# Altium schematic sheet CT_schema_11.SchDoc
size 386 x 278 mm
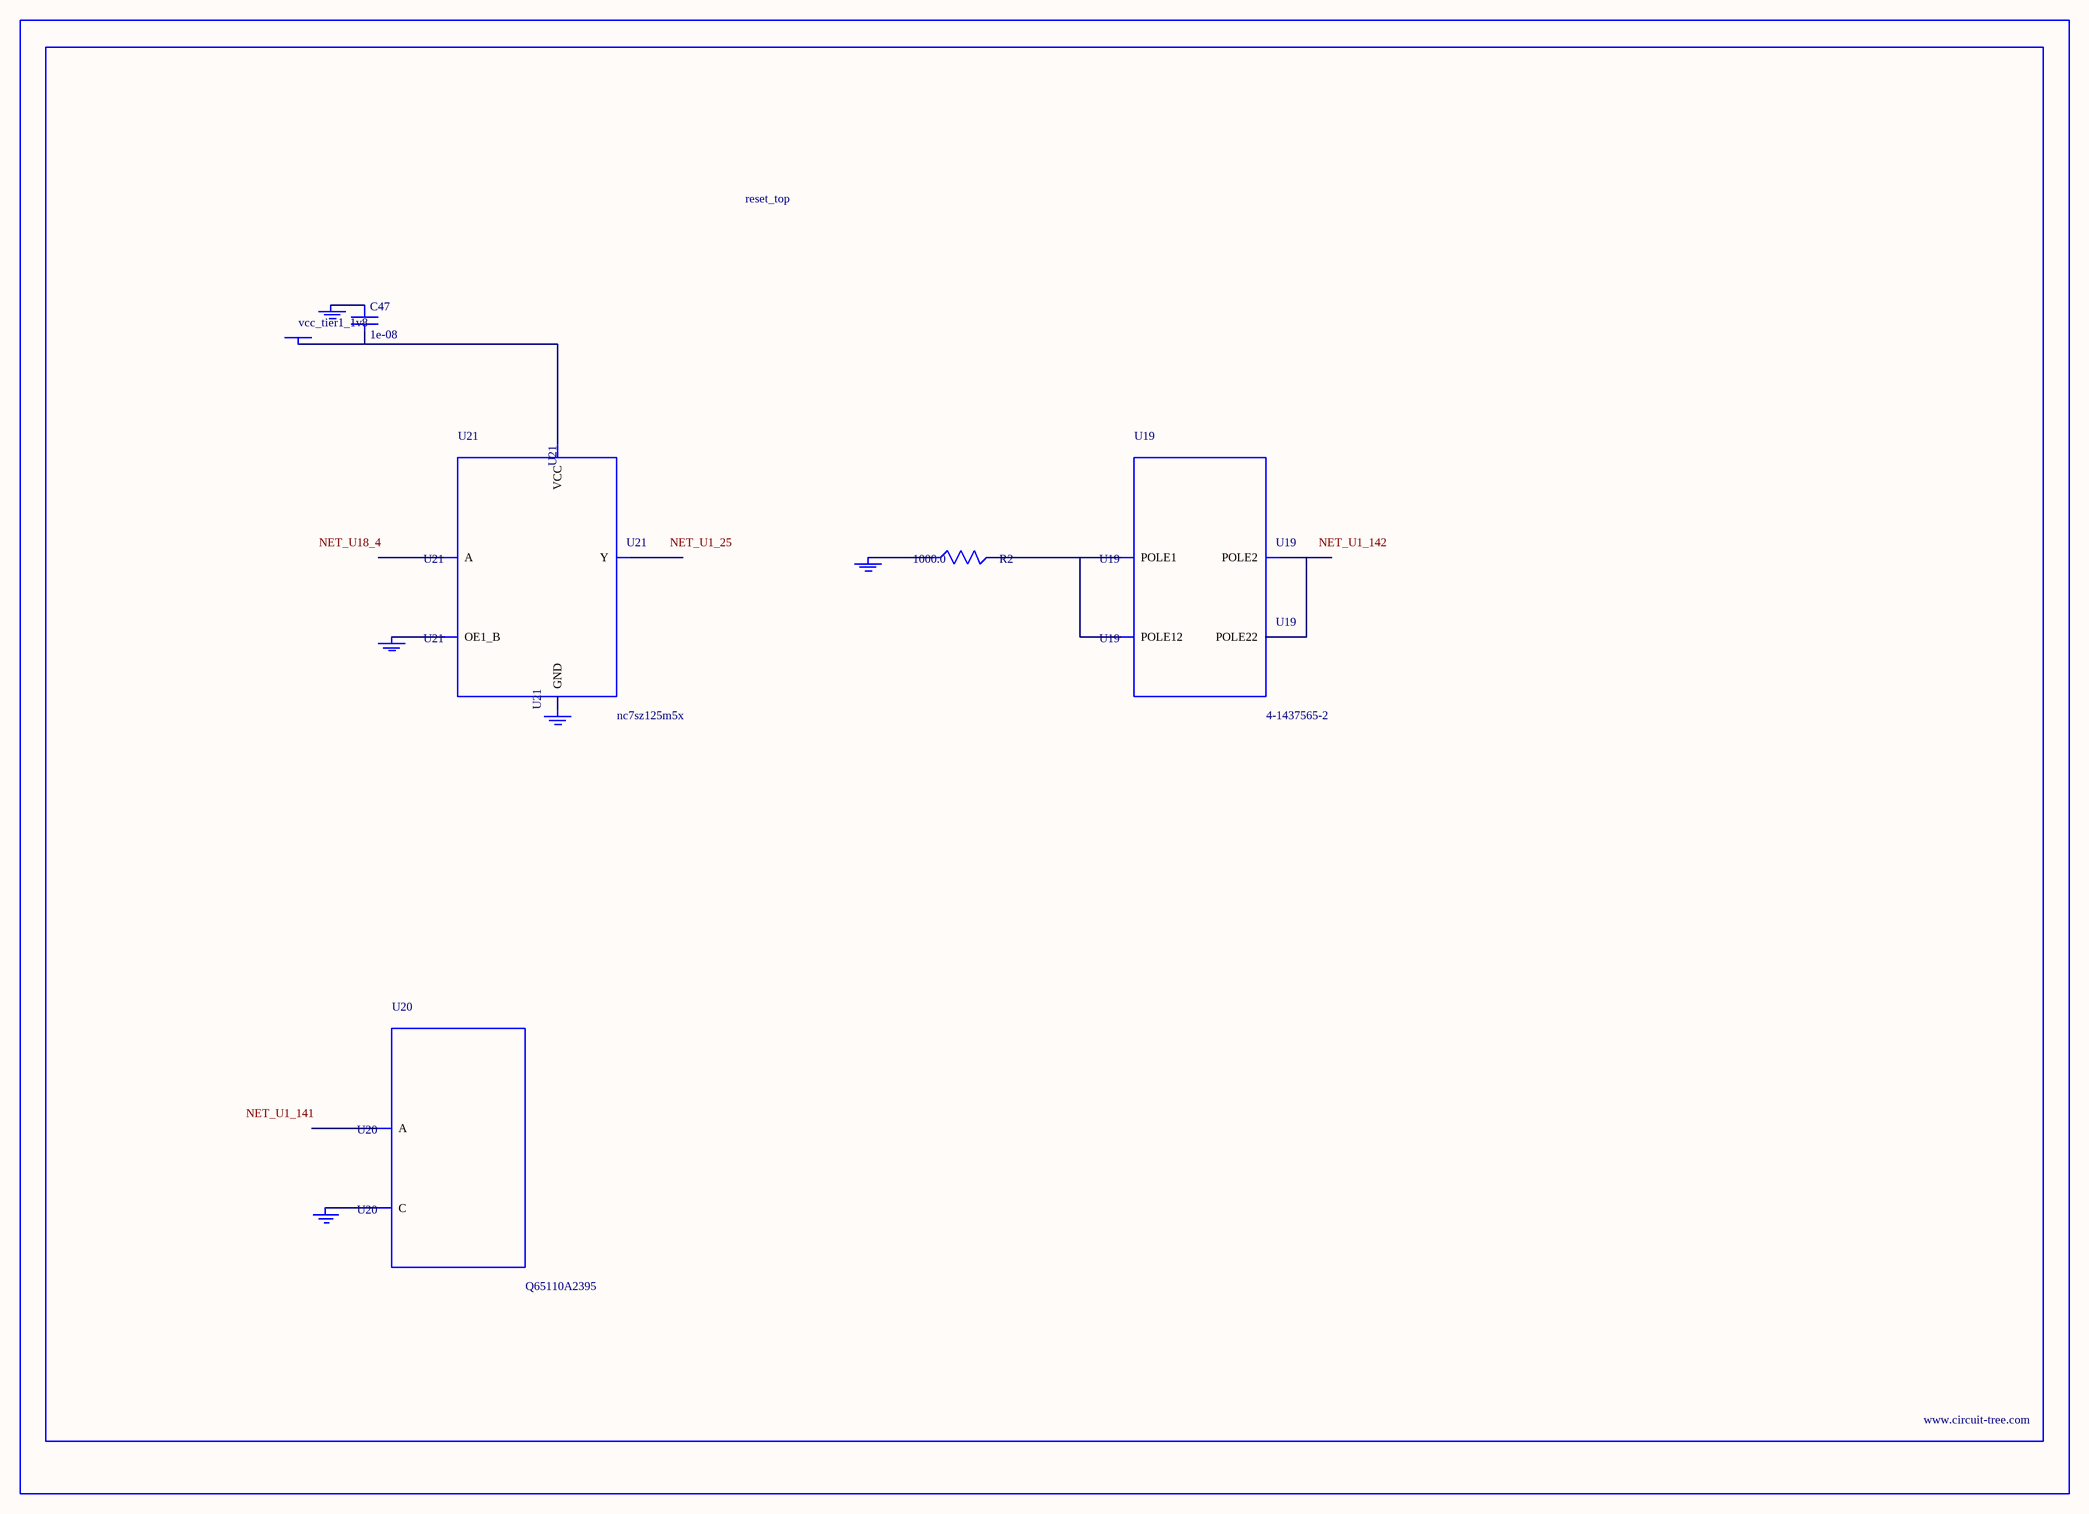
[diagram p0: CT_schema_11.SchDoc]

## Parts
BORDER10  (no value)
C47  1e-08  [C0402]
GND_INSTANCE_10_0  (no value)
GND_INSTANCE_10_1  (no value)
GND_INSTANCE_10_2  (no value)
GND_INSTANCE_10_3  (no value)
GND_INSTANCE_10_4  (no value)
POWER_INSTANCE_10_0  vcc_tier1_1v8
R2  1000.0  [R0603]
U19  4-1437565-2  [SW_4-1437565-2]
U20  Q65110A2395  [LGM67K-G1J2-24-Z]
U21  nc7sz125m5x  [NC7SZ125M5X]

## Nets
NetC47_1: C47.1 GND_INSTANCE_10_2.0(GND)
NetC47_2: C47.2 POWER_INSTANCE_10_0.0(PWR) U21.5(VCC)
NetGND_INSTANCE_10_0_0: GND_INSTANCE_10_0.0(GND) R2.1
NetGND_INSTANCE_10_1_0: GND_INSTANCE_10_1.0(GND) U20.C
NetGND_INSTANCE_10_3_0: GND_INSTANCE_10_3.0(GND) U21.1(OE1_B)
NetGND_INSTANCE_10_4_0: GND_INSTANCE_10_4.0(GND) U21.3(GND)
NetR2_2: R2.2 U19.1(POLE1) U19.2(POLE12)
NetU19_3: U19.3(POLE2) U19.4(POLE22)

Not connected (* = marked no-connect by the designer): U20 A; U21 2(A) 4(Y)

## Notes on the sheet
- Labels drawn without touching a wire or pin: NET_U1_25, NET_U1_141, NET_U1_142, NET_U18_4

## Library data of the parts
BORDER10 = BORDER_PAGE10
C47 = C0402C103K3RAC
GND_INSTANCE_10_0-GND_INSTANCE_10_4 = GND
POWER_INSTANCE_10_0 = PWR
R2 = RC0603JR-071KL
